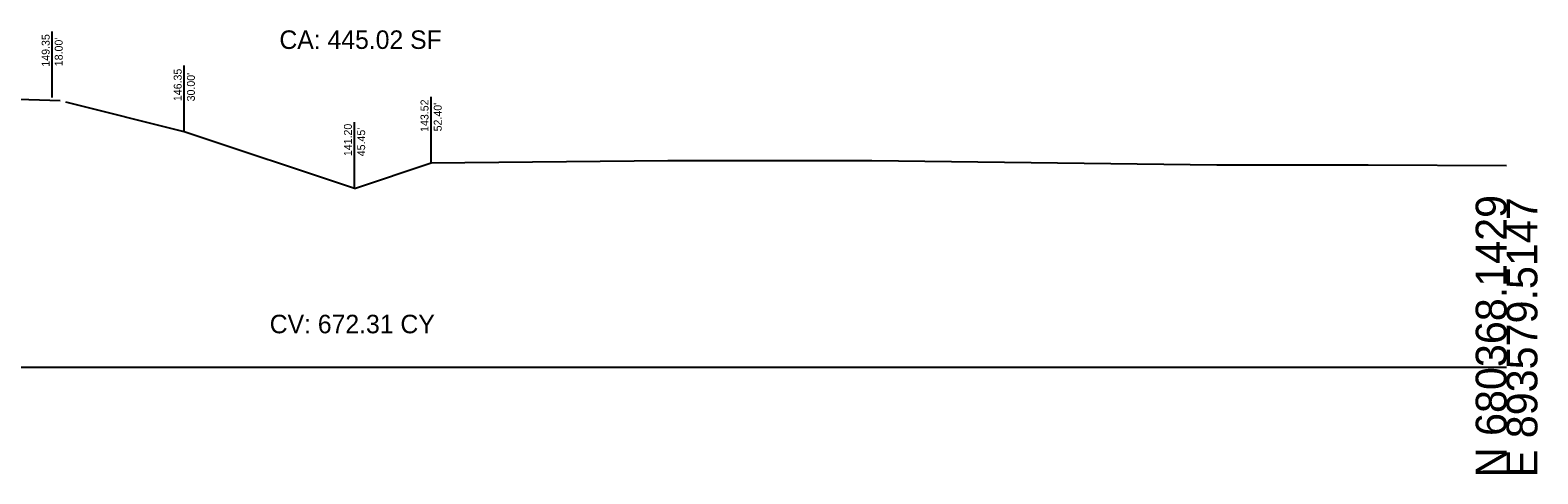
# Model space of a CAD drawing. Extents: x -100 to 4303, y -13 to 10775.
# Drawn here: x 166 to 302.8, y 9490.3 to 9530.6 of the extents above; entities that cross this region are included whole.
import ezdxf

# ---------------------------------------------------------------- set-up
doc = ezdxf.new("R2010")
doc.units = 0
for name, color, linetype in [('DTM_X_GROUND', 7, 'Continuous'), ('XS_CELL', 7, 'Continuous'), ('XS_P_TX_CLEARZONE', 7, 'Continuous'), ('XS_SHEET_EW_TX_AREA', 7, 'Continuous'), ('XS_SHEET_EW_TX_VOLUME', 7, 'Continuous')]:
    doc.layers.add(name, color=color, linetype=linetype)

msp = doc.modelspace()

# ---------------------------------------------------------------- linework, layer by layer
at = {"layer": 'DTM_X_GROUND'}
msp.add_line((164, 9524.32), (168.73, 9524.17), dxfattribs=at)
for points in [[(195.45, 9516.2), (180, 9521.35), (180, 9521.35), (180, 9521.35), (169.24, 9524.04)], [(195.45, 9516.2), (202.4, 9518.52)], [(202.4, 9518.52), (223.87, 9518.75), (242.4, 9518.73), (273.71, 9518.35), (287.43, 9518.35), (300, 9518.29)]]:
    msp.add_lwpolyline(points, dxfattribs=at)
at = {"layer": 'XS_CELL'}
msp.add_line((150, 9500), (300, 9500), dxfattribs=at)
msp.add_line((150, 9500), (300, 9500), dxfattribs=at)
at = {"layer": 'XS_P_TX_CLEARZONE'}
for p, q in [((168, 9524.44), (168, 9530.44)), ((180, 9521.35), (180, 9527.35)), ((180, 9521.35), (180, 9527.35)), ((202.4, 9518.52), (202.4, 9524.52)), ((202.4, 9518.52), (202.4, 9524.52)), ((202.4, 9518.52), (202.4, 9524.52)), ((195.45, 9516.2), (195.45, 9522.2)), ((195.45, 9516.2), (195.45, 9522.2)), ((195.45, 9516.2), (195.45, 9522.2))]:
    msp.add_line(p, q, dxfattribs=at)

# ---------------------------------------------------------------- texts
at = {"layer": 'XS_CELL'}
for s, p in [('N 680368.1429', (300, 9490)), ('N 680368.1429', (300, 9490)), ('E 893579.5147', (302.8, 9490)), ('E 893579.5147', (302.8, 9490))]:
    msp.add_text(s, height=2.8, rotation=90, dxfattribs=at).set_placement(p)
at = {"layer": 'XS_P_TX_CLEARZONE'}
for s, p in [('149.35', (167.78, 9527.25)), ("18.00'", (168.96, 9527.29)), ('146.35', (179.76, 9524.12)), ('146.35', (179.76, 9524.12)), ("30.00'", (180.96, 9524.1)), ("30.00'", (180.96, 9524.1)), ('143.52', (202.16, 9521.33)), ('143.52', (202.16, 9521.33)), ('143.52', (202.16, 9521.33)), ("52.40'", (203.36, 9521.38)), ("52.40'", (203.36, 9521.38)), ("52.40'", (203.36, 9521.38)), ('141.20', (195.21, 9519.13)), ('141.20', (195.21, 9519.13)), ('141.20', (195.21, 9519.13)), ("45.45'", (196.41, 9519.12)), ("45.45'", (196.41, 9519.12)), ("45.45'", (196.41, 9519.12))]:
    msp.add_text(s, height=0.72, rotation=90, dxfattribs=at).set_placement(p)
at = {"layer": 'XS_SHEET_EW_TX_AREA'}
msp.add_text('CA: 445.02 SF', height=1.68, dxfattribs=at).set_placement((188.63, 9528.86))
at = {"layer": 'XS_SHEET_EW_TX_VOLUME'}
msp.add_text('CV: 672.31 CY', height=1.68, dxfattribs=at).set_placement((187.75, 9503.06))

doc.saveas('drawing.dxf')
